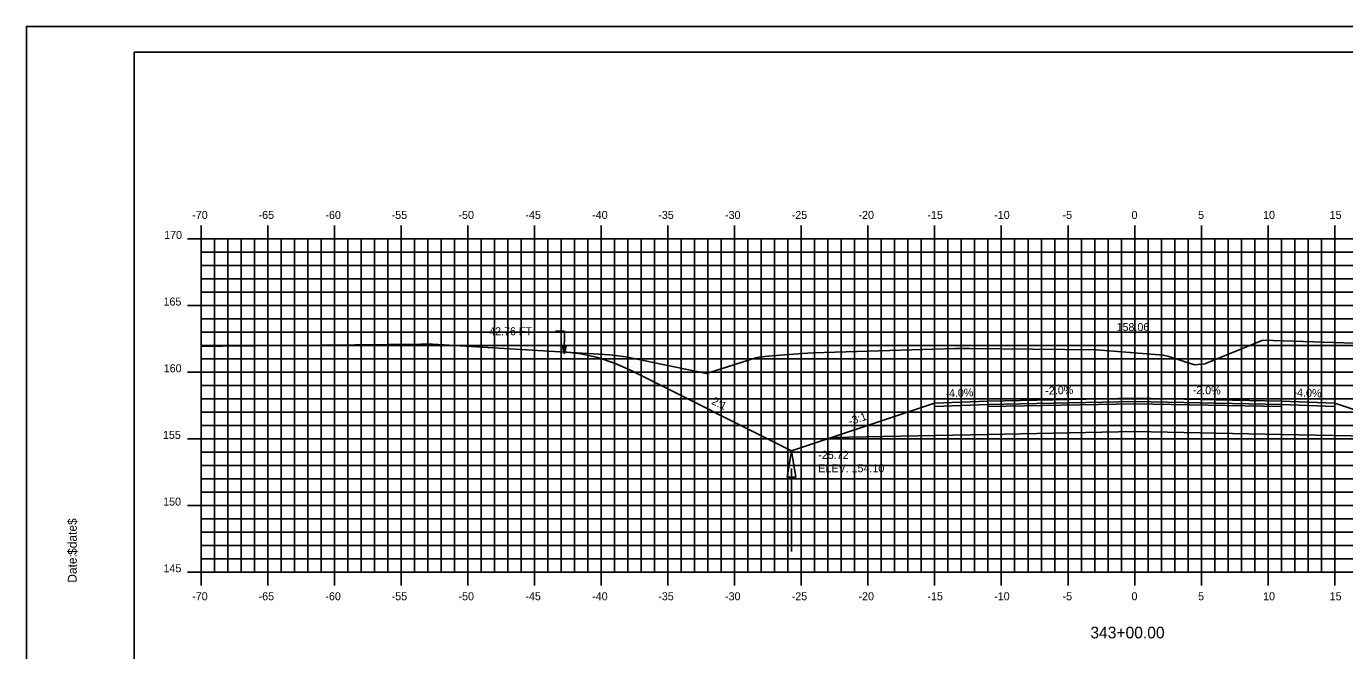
# Model space of a CAD drawing. Extents: x 1143198 to 1143368, y 608981 to 609091.
# Drawn here: x 1143198.2 to 1143297.1, y 609044.5 to 609091.3 of the extents above; entities that cross this region are included whole.
import ezdxf

# ---------------------------------------------------------------- set-up
doc = ezdxf.new("R2010")
doc.units = 0
for name, color, linetype in [('ANNOTATION', 7, 'Continuous'), ('BORDER', 7, 'Continuous'), ('D_Drainage_Ditch_Line', 7, 'Continuous'), ('D_Roadway_Centerline', 7, 'Continuous'), ('D_Roadway_Centerline_Text', 7, 'Continuous'), ('D_Roadway_Edge_Shoulder', 7, 'Continuous'), ('D_Roadway_Edge_TW', 7, 'Continuous'), ('D_Roadway_Pavement', 7, 'Continuous'), ('D_Roadway_SlopeLines', 7, 'Continuous'), ('D_Roadway_SubGrade', 7, 'Continuous'), ('D_Text_Standard', 7, 'Continuous'), ('H_V ANNOTATION', 7, 'Continuous'), ('MAJOR', 7, 'Continuous'), ('MINOR', 7, 'Continuous'), ('PLOT BOUNDARY', 7, 'Continuous'), ('S_Roadway_Centerline', 7, 'Continuous')]:
    doc.layers.add(name, color=color, linetype=linetype)

msp = doc.modelspace()

# ---------------------------------------------------------------- linework, layer by layer
msp.add_lwpolyline([(1143238.561, 609066.856), (1143239.811, 609066.712), (1143241.061, 609066.431), (1143242.311, 609066.013), (1143243.561, 609065.457), (1143255.598, 609059.438), (1143258.598, 609060.438), (1143266.322, 609063.012), (1143266.323, 609063.012), (1143270.323, 609063.172), (1143281.323, 609063.392), (1143292.323, 609063.172), (1143296.323, 609063.012), (1143304.047, 609060.438), (1143307.047, 609059.438), (1143319.789, 609065.809), (1143321.039, 609066.354), (1143322.289, 609066.738), (1143323.539, 609066.962), (1143324.789, 609067.025)])
at = {"layer": 'BORDER'}
msp.add_lwpolyline([(1143206.323, 608984.335), (1143366.323, 608984.335), (1143366.323, 609089.335), (1143206.323, 609089.335)], close=True, dxfattribs=at)
at = {"layer": 'D_Drainage_Ditch_Line'}
msp.add_line((1143255.599, 609058.126), (1143255.598, 609051.882), dxfattribs=at)
msp.add_lwpolyline([(1143255.927, 609057.469), (1143255.27, 609057.469), (1143255.598, 609059.438)], close=True, dxfattribs=at)
at = {"layer": 'D_Roadway_Edge_Shoulder'}
for points in [[(1143270.323, 609063.172), (1143266.323, 609063.012), (1143266.323, 609062.762), (1143270.323, 609062.922)], [(1143292.323, 609063.172), (1143296.323, 609063.012), (1143296.323, 609062.762), (1143292.323, 609062.922)]]:
    msp.add_lwpolyline(points, close=True, dxfattribs=at)
at = {"layer": 'D_Roadway_Edge_TW'}
msp.add_lwpolyline([(1143270.323, 609062.922), (1143270.323, 609063.172), (1143281.323, 609063.392), (1143292.323, 609063.172), (1143292.323, 609062.922), (1143281.323, 609063.142)], close=True, dxfattribs=at)
at = {"layer": 'D_Roadway_Pavement'}
msp.add_lwpolyline([(1143270.323, 609062.756), (1143270.323, 609062.922), (1143281.323, 609063.142), (1143292.323, 609062.922), (1143292.323, 609062.756), (1143281.323, 609062.976)], close=True, dxfattribs=at)
at = {"layer": 'D_Roadway_SlopeLines'}
for points in [[(1143255.598, 609059.438), (1143243.561, 609065.457), (1143242.311, 609066.013), (1143241.061, 609066.431), (1143239.811, 609066.712), (1143238.561, 609066.856)], [(1143258.598, 609060.438), (1143255.598, 609059.438)]]:
    msp.add_lwpolyline(points, dxfattribs=at)
at = {"layer": 'D_Roadway_SubGrade'}
for points in [[(1143270.323, 609062.756), (1143270.323, 609062.922), (1143266.323, 609062.762), (1143266.323, 609063.012), (1143266.322, 609063.012), (1143258.598, 609060.438), (1143270.323, 609060.672)], [(1143270.323, 609060.672), (1143270.323, 609062.756), (1143281.323, 609062.976), (1143292.323, 609062.756), (1143292.323, 609060.672), (1143281.323, 609060.892)], [(1143292.323, 609062.756), (1143292.323, 609062.922), (1143296.323, 609062.762), (1143296.323, 609063.012), (1143296.323, 609063.012), (1143304.047, 609060.438), (1143292.323, 609060.672)]]:
    msp.add_lwpolyline(points, close=True, dxfattribs=at)
at = {"layer": 'D_Text_Standard'}
msp.add_lwpolyline([(1143238.561, 609066.707), (1143238.569, 609068.412), (1143237.889, 609068.412)], dxfattribs=at)
msp.add_lwpolyline([(1143238.561, 609066.707), (1143238.418, 609067.29), (1143238.709, 609067.288)], close=True, dxfattribs=at)
at = {"layer": 'MAJOR'}
for p, q in [((1143211.323, 609076.337), (1143211.323, 609075.335)), ((1143216.323, 609076.337), (1143216.323, 609075.335)), ((1143221.323, 609076.337), (1143221.323, 609075.335)), ((1143226.323, 609076.337), (1143226.323, 609075.335)), ((1143231.323, 609076.337), (1143231.323, 609075.335)), ((1143236.323, 609076.337), (1143236.323, 609075.335)), ((1143241.323, 609076.337), (1143241.323, 609075.335)), ((1143246.323, 609076.337), (1143246.323, 609075.335)), ((1143251.323, 609076.337), (1143251.323, 609075.335)), ((1143256.323, 609076.337), (1143256.323, 609075.335)), ((1143261.323, 609076.337), (1143261.323, 609075.335)), ((1143266.323, 609076.337), (1143266.323, 609075.335)), ((1143271.323, 609076.337), (1143271.323, 609075.335)), ((1143276.323, 609076.337), (1143276.323, 609075.335)), ((1143281.323, 609076.337), (1143281.323, 609075.335)), ((1143286.323, 609076.337), (1143286.323, 609075.335)), ((1143291.323, 609076.337), (1143291.323, 609075.335)), ((1143296.323, 609076.337), (1143296.323, 609075.335)), ((1143210.321, 609075.335), (1143211.323, 609075.335)), ((1143211.323, 609075.335), (1143351.323, 609075.335)), ((1143211.323, 609050.335), (1143211.323, 609075.335)), ((1143211.323, 609050.335), (1143211.323, 609075.335)), ((1143211.323, 609075.335), (1143351.323, 609075.335)), ((1143216.323, 609050.335), (1143216.323, 609075.335)), ((1143221.323, 609050.335), (1143221.323, 609075.335)), ((1143226.323, 609050.335), (1143226.323, 609075.335)), ((1143231.323, 609050.335), (1143231.323, 609075.335)), ((1143236.323, 609050.335), (1143236.323, 609075.335)), ((1143241.323, 609050.335), (1143241.323, 609075.335)), ((1143246.323, 609050.335), (1143246.323, 609075.335)), ((1143251.323, 609050.335), (1143251.323, 609075.335)), ((1143256.323, 609050.335), (1143256.323, 609075.335)), ((1143261.323, 609050.335), (1143261.323, 609075.335)), ((1143266.323, 609050.335), (1143266.323, 609075.335)), ((1143271.323, 609050.335), (1143271.323, 609075.335)), ((1143276.323, 609050.335), (1143276.323, 609075.335)), ((1143281.323, 609050.335), (1143281.323, 609075.335)), ((1143286.323, 609050.335), (1143286.323, 609075.335)), ((1143291.323, 609050.335), (1143291.323, 609075.335)), ((1143296.323, 609050.335), (1143296.323, 609075.335)), ((1143210.321, 609070.335), (1143211.323, 609070.335)), ((1143211.323, 609070.335), (1143351.323, 609070.335)), ((1143210.321, 609065.335), (1143211.323, 609065.335)), ((1143211.323, 609065.335), (1143351.323, 609065.335)), ((1143210.321, 609060.335), (1143211.323, 609060.335)), ((1143211.323, 609060.335), (1143351.323, 609060.335)), ((1143210.321, 609055.335), (1143211.323, 609055.335)), ((1143211.323, 609055.335), (1143351.323, 609055.335)), ((1143210.321, 609050.335), (1143211.323, 609050.335)), ((1143211.323, 609050.335), (1143351.323, 609050.335)), ((1143211.323, 609050.335), (1143351.323, 609050.335)), ((1143211.323, 609049.333), (1143211.323, 609050.335)), ((1143216.323, 609049.333), (1143216.323, 609050.335)), ((1143221.323, 609049.333), (1143221.323, 609050.335)), ((1143226.323, 609049.333), (1143226.323, 609050.335)), ((1143231.323, 609049.333), (1143231.323, 609050.335)), ((1143236.323, 609049.333), (1143236.323, 609050.335)), ((1143241.323, 609049.333), (1143241.323, 609050.335)), ((1143246.323, 609049.333), (1143246.323, 609050.335)), ((1143251.323, 609049.333), (1143251.323, 609050.335)), ((1143256.323, 609049.333), (1143256.323, 609050.335)), ((1143261.323, 609049.333), (1143261.323, 609050.335)), ((1143266.323, 609049.333), (1143266.323, 609050.335)), ((1143271.323, 609049.333), (1143271.323, 609050.335)), ((1143276.323, 609049.333), (1143276.323, 609050.335)), ((1143281.323, 609049.333), (1143281.323, 609050.335)), ((1143286.323, 609049.333), (1143286.323, 609050.335)), ((1143291.323, 609049.333), (1143291.323, 609050.335)), ((1143296.323, 609049.333), (1143296.323, 609050.335))]:
    msp.add_line(p, q, dxfattribs=at)
at = {"layer": 'MINOR'}
for p, q in [((1143212.323, 609050.335), (1143212.323, 609075.335)), ((1143213.323, 609050.335), (1143213.323, 609075.335)), ((1143214.323, 609050.335), (1143214.323, 609075.335)), ((1143215.323, 609050.335), (1143215.323, 609075.335)), ((1143217.323, 609050.335), (1143217.323, 609075.335)), ((1143218.323, 609050.335), (1143218.323, 609075.335)), ((1143219.323, 609050.335), (1143219.323, 609075.335)), ((1143220.323, 609050.335), (1143220.323, 609075.335)), ((1143222.323, 609050.335), (1143222.323, 609075.335)), ((1143223.323, 609050.335), (1143223.323, 609075.335)), ((1143224.323, 609050.335), (1143224.323, 609075.335)), ((1143225.323, 609050.335), (1143225.323, 609075.335)), ((1143227.323, 609050.335), (1143227.323, 609075.335)), ((1143228.323, 609050.335), (1143228.323, 609075.335)), ((1143229.323, 609050.335), (1143229.323, 609075.335)), ((1143230.323, 609050.335), (1143230.323, 609075.335)), ((1143232.323, 609050.335), (1143232.323, 609075.335)), ((1143233.323, 609050.335), (1143233.323, 609075.335)), ((1143234.323, 609050.335), (1143234.323, 609075.335)), ((1143235.323, 609050.335), (1143235.323, 609075.335)), ((1143237.323, 609050.335), (1143237.323, 609075.335)), ((1143238.323, 609050.335), (1143238.323, 609075.335)), ((1143239.323, 609050.335), (1143239.323, 609075.335)), ((1143240.323, 609050.335), (1143240.323, 609075.335)), ((1143242.323, 609050.335), (1143242.323, 609075.335)), ((1143243.323, 609050.335), (1143243.323, 609075.335)), ((1143244.323, 609050.335), (1143244.323, 609075.335)), ((1143245.323, 609050.335), (1143245.323, 609075.335)), ((1143247.323, 609050.335), (1143247.323, 609075.335)), ((1143248.323, 609050.335), (1143248.323, 609075.335)), ((1143249.323, 609050.335), (1143249.323, 609075.335)), ((1143250.323, 609050.335), (1143250.323, 609075.335)), ((1143252.323, 609050.335), (1143252.323, 609075.335)), ((1143253.323, 609050.335), (1143253.323, 609075.335)), ((1143254.323, 609050.335), (1143254.323, 609075.335)), ((1143255.323, 609050.335), (1143255.323, 609075.335)), ((1143257.323, 609050.335), (1143257.323, 609075.335)), ((1143258.323, 609050.335), (1143258.323, 609075.335)), ((1143259.323, 609050.335), (1143259.323, 609075.335)), ((1143260.323, 609050.335), (1143260.323, 609075.335)), ((1143262.323, 609050.335), (1143262.323, 609075.335)), ((1143263.323, 609050.335), (1143263.323, 609075.335)), ((1143264.323, 609050.335), (1143264.323, 609075.335)), ((1143265.323, 609050.335), (1143265.323, 609075.335)), ((1143267.323, 609050.335), (1143267.323, 609075.335)), ((1143268.323, 609050.335), (1143268.323, 609075.335)), ((1143269.323, 609050.335), (1143269.323, 609075.335)), ((1143270.323, 609050.335), (1143270.323, 609075.335)), ((1143272.323, 609050.335), (1143272.323, 609075.335)), ((1143273.323, 609050.335), (1143273.323, 609075.335)), ((1143274.323, 609050.335), (1143274.323, 609075.335)), ((1143275.323, 609050.335), (1143275.323, 609075.335)), ((1143277.323, 609050.335), (1143277.323, 609075.335)), ((1143278.323, 609050.335), (1143278.323, 609075.335)), ((1143279.323, 609050.335), (1143279.323, 609075.335)), ((1143280.323, 609050.335), (1143280.323, 609075.335)), ((1143282.323, 609050.335), (1143282.323, 609075.335)), ((1143283.323, 609050.335), (1143283.323, 609075.335)), ((1143284.323, 609050.335), (1143284.323, 609075.335)), ((1143285.323, 609050.335), (1143285.323, 609075.335)), ((1143287.323, 609050.335), (1143287.323, 609075.335)), ((1143288.323, 609050.335), (1143288.323, 609075.335)), ((1143289.323, 609050.335), (1143289.323, 609075.335)), ((1143290.323, 609050.335), (1143290.323, 609075.335)), ((1143292.323, 609050.335), (1143292.323, 609075.335)), ((1143293.323, 609050.335), (1143293.323, 609075.335)), ((1143294.323, 609050.335), (1143294.323, 609075.335)), ((1143295.323, 609050.335), (1143295.323, 609075.335)), ((1143211.323, 609074.335), (1143351.323, 609074.335)), ((1143211.323, 609074.335), (1143212.325, 609074.335)), ((1143211.323, 609073.335), (1143351.323, 609073.335)), ((1143211.323, 609073.335), (1143212.325, 609073.335)), ((1143211.323, 609072.335), (1143351.323, 609072.335)), ((1143211.323, 609072.335), (1143212.325, 609072.335)), ((1143211.323, 609071.335), (1143351.323, 609071.335)), ((1143211.323, 609071.335), (1143212.325, 609071.335)), ((1143211.323, 609069.335), (1143351.323, 609069.335)), ((1143211.323, 609069.335), (1143212.325, 609069.335)), ((1143211.323, 609068.335), (1143351.323, 609068.335)), ((1143211.323, 609068.335), (1143212.325, 609068.335)), ((1143211.323, 609067.335), (1143351.323, 609067.335)), ((1143211.323, 609067.335), (1143212.325, 609067.335)), ((1143211.323, 609066.335), (1143351.323, 609066.335)), ((1143211.323, 609066.335), (1143212.325, 609066.335)), ((1143211.323, 609064.335), (1143351.323, 609064.335)), ((1143211.323, 609064.335), (1143212.325, 609064.335)), ((1143211.323, 609063.335), (1143351.323, 609063.335)), ((1143211.323, 609063.335), (1143212.325, 609063.335)), ((1143211.323, 609062.335), (1143351.323, 609062.335)), ((1143211.323, 609062.335), (1143212.325, 609062.335)), ((1143211.323, 609061.335), (1143351.323, 609061.335)), ((1143211.323, 609061.335), (1143212.325, 609061.335)), ((1143211.323, 609059.335), (1143351.323, 609059.335)), ((1143211.323, 609059.335), (1143212.325, 609059.335)), ((1143211.323, 609058.335), (1143351.323, 609058.335)), ((1143211.323, 609058.335), (1143212.325, 609058.335)), ((1143211.323, 609057.335), (1143351.323, 609057.335)), ((1143211.323, 609057.335), (1143212.325, 609057.335)), ((1143211.323, 609056.335), (1143351.323, 609056.335)), ((1143211.323, 609056.335), (1143212.325, 609056.335)), ((1143211.323, 609054.335), (1143351.323, 609054.335)), ((1143211.323, 609054.335), (1143212.325, 609054.335)), ((1143211.323, 609053.335), (1143351.323, 609053.335)), ((1143211.323, 609053.335), (1143212.325, 609053.335)), ((1143211.323, 609052.335), (1143351.323, 609052.335)), ((1143211.323, 609052.335), (1143212.325, 609052.335)), ((1143211.323, 609051.335), (1143351.323, 609051.335)), ((1143211.323, 609051.335), (1143212.325, 609051.335))]:
    msp.add_line(p, q, dxfattribs=at)
at = {"layer": 'PLOT BOUNDARY'}
msp.add_lwpolyline([(1143198.23, 608981.276), (1143368.23, 608981.276), (1143368.23, 609091.276), (1143198.23, 609091.276)], close=True, dxfattribs=at)
at = {"layer": 'S_Roadway_Centerline'}
msp.add_lwpolyline([(1143211.323, 609067.284), (1143212.932, 609067.302), (1143227.791, 609067.451), (1143228.668, 609067.444), (1143241.963, 609066.653), (1143243.162, 609066.487), (1143249.208, 609065.23), (1143252.922, 609066.422), (1143253.3, 609066.495), (1143254.772, 609066.625), (1143256.406, 609066.751), (1143257.227, 609066.788), (1143267.886, 609067.116), (1143268.92, 609067.11), (1143278.456, 609067.011), (1143279.109, 609066.96), (1143283.468, 609066.626), (1143283.88, 609066.529), (1143285.799, 609065.88), (1143286.587, 609065.969), (1143290.923, 609067.734), (1143309.881, 609067.108)], dxfattribs=at)

# ---------------------------------------------------------------- texts
at = {"layer": 'ANNOTATION'}
for s, rotation, p in [('-4.0%', 2.29061, (1143267.139, 609063.446)), ('-2.0%', 1.14576, (1143274.626, 609063.659)), ('-2.0%', 358.85424, (1143285.666, 609063.706)), ('-4.0%', 357.70939, (1143293.219, 609063.537)), ('2:1', 333.43495, (1143249.547, 609062.982)), ('-3:1', 18.43482, (1143259.977, 609061.352))]:
    msp.add_text(s, height=0.6, rotation=rotation, dxfattribs=at).set_placement(p)
at = {"layer": 'BORDER'}
for s, p in [('$date$', (1143202.008, 609051.64)), ('Date:', (1143202.008, 609049.552))]:
    msp.add_text(s, height=0.6696, rotation=90, dxfattribs=at).set_placement(p)
at = {"layer": 'D_Roadway_Centerline'}
for s, p in [('C', (1143281.318, 609063.392)), ('L', (1143281.323, 609063.385))]:
    msp.add_text(s, height=0.0146, dxfattribs=at).set_placement(p)
at = {"layer": 'D_Roadway_Centerline_Text'}
msp.add_text('158.06', height=0.6, dxfattribs=at).set_placement((1143279.964, 609068.424))
at = {"layer": 'D_Text_Standard'}
for s, p in [('-42.76 FT', (1143232.659, 609068.112)), ('-25.72', (1143257.599, 609058.838)), ('ELEV. 154.10', (1143257.599, 609057.836))]:
    msp.add_text(s, height=0.6, dxfattribs=at).set_placement(p)
at = {"layer": 'H_V ANNOTATION'}
for s, height, p in [('-70', 0.6, (1143210.665, 609076.835)), ('-65', 0.6, (1143215.641, 609076.835)), ('-60', 0.6, (1143220.649, 609076.835)), ('-55', 0.6, (1143225.619, 609076.835)), ('-50', 0.6, (1143230.627, 609076.835)), ('-45', 0.6, (1143235.641, 609076.835)), ('-40', 0.6, (1143240.649, 609076.835)), ('-35', 0.6, (1143245.603, 609076.835)), ('-30', 0.6, (1143250.611, 609076.835)), ('-25', 0.6, (1143255.609, 609076.835)), ('-20', 0.6, (1143260.617, 609076.835)), ('-15', 0.6, (1143265.78, 609076.835)), ('-10', 0.6, (1143270.788, 609076.835)), ('-5', 0.6, (1143275.914, 609076.835)), ('0', 0.6, (1143281.082, 609076.835)), ('5', 0.6, (1143286.074, 609076.835)), ('10', 0.6, (1143290.948, 609076.835)), ('15', 0.6, (1143295.94, 609076.835)), ('170', 0.6, (1143208.56, 609075.335)), ('165', 0.6, (1143208.512, 609070.335)), ('160', 0.6, (1143208.528, 609065.335)), ('155', 0.6, (1143208.469, 609060.335)), ('150', 0.6, (1143208.485, 609055.335)), ('145', 0.6, (1143208.512, 609050.335)), ('-70', 0.6, (1143210.665, 609048.235)), ('-65', 0.6, (1143215.641, 609048.235)), ('-60', 0.6, (1143220.649, 609048.235)), ('-55', 0.6, (1143225.619, 609048.235)), ('-50', 0.6, (1143230.627, 609048.235)), ('-45', 0.6, (1143235.641, 609048.235)), ('-40', 0.6, (1143240.649, 609048.235)), ('-35', 0.6, (1143245.603, 609048.235)), ('-30', 0.6, (1143250.611, 609048.235)), ('-25', 0.6, (1143255.609, 609048.235)), ('-20', 0.6, (1143260.617, 609048.235)), ('-15', 0.6, (1143265.78, 609048.235)), ('-10', 0.6, (1143270.788, 609048.235)), ('-5', 0.6, (1143275.914, 609048.235)), ('0', 0.6, (1143281.082, 609048.235)), ('5', 0.6, (1143286.074, 609048.235)), ('10', 0.6, (1143290.948, 609048.235)), ('15', 0.6, (1143295.94, 609048.235)), ('343+00.00', 0.875, (1143277.999, 609045.378))]:
    msp.add_text(s, height=height, dxfattribs=at).set_placement(p)
at = {"layer": 'MAJOR'}
msp.add_text('-', height=0.006, dxfattribs=at).set_placement((1143211.319, 609050.335))
at = {"layer": 'S_Roadway_Centerline'}
for s, p in [('L', (1143267.878, 609067.109)), ('C', (1143267.881, 609067.116))]:
    msp.add_text(s, height=0.0146, dxfattribs=at).set_placement(p)

doc.saveas('drawing.dxf')
